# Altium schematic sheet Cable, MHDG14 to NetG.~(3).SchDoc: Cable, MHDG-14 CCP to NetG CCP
size B; ApprovedBy: Hans Thomas; CheckedBy: Hans Thomas; Author: Hans Thomas; DrawnBy: Hans Thomas; Engineer: Hans Thomas; Organization: MBARI; DocumentNumber: 100221138; Revision: A; SheetNumber: 1; SheetTotal: 1; PageSetup: Record=PageOptions¦CenterHorizontal=True¦CenterVertical=True¦PrintScale=0.72¦XCorrection=1.00¦YCorrection=1.00¦PrintKind=0¦BorderSize=5000000¦LeftOffset=0¦BottomOffset=0¦Orientation=2¦PaperLength=2794¦PaperWidth=2159¦Scale=100¦PaperSource=15¦PrintQuality=-3¦MediaType=1¦DitherType=0¦PrintScaleMode=1¦PaperKind=Letter (8.5 x 11 in)¦PaperIndex=1
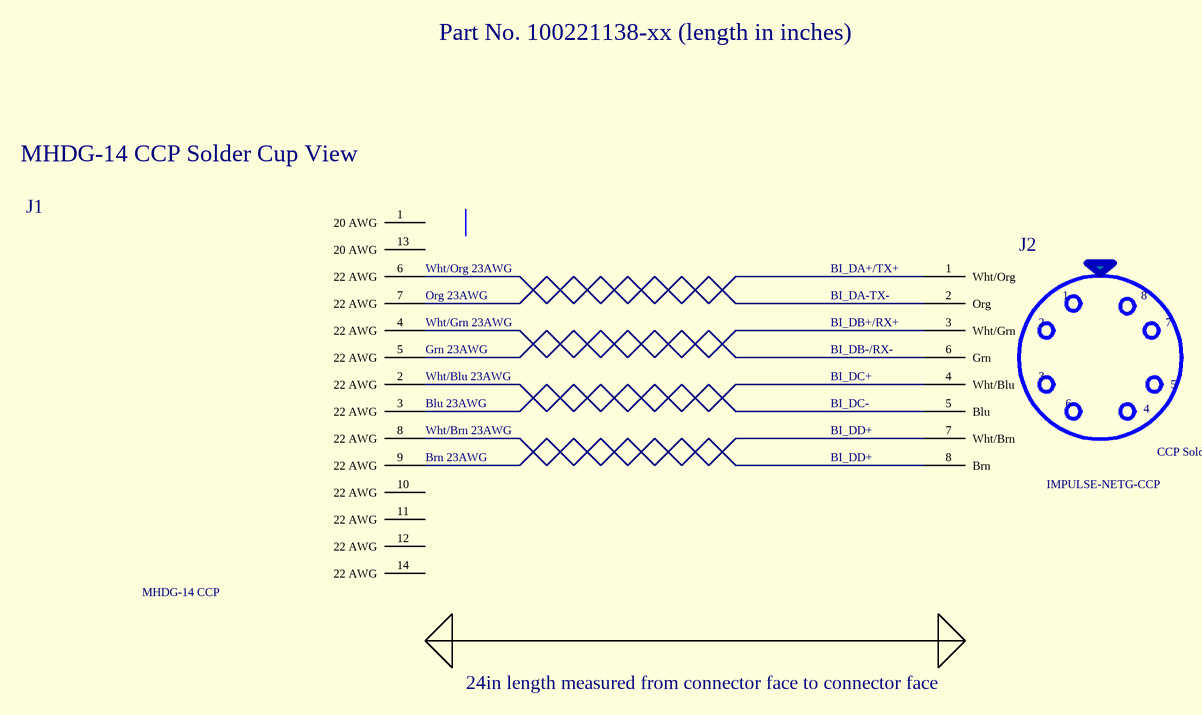
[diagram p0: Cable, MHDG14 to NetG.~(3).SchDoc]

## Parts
J1  MHDG-14 CCP
J2  IMPULSE-NETG-CCP

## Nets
NetJ1_2: J1.2(22_AWG) J2.4(Wht/Blu)
NetJ1_3: J1.3(22_AWG) J2.5(Blu)
NetJ1_4: J1.4(22_AWG) J2.3(Wht/Grn)
NetJ1_5: J1.5(22_AWG) J2.6(Grn)
NetJ1_6: J1.6(22_AWG) J2.1(Wht/Org)
NetJ1_7: J1.7(22_AWG) J2.2(Org)
NetJ1_8: J1.8(22_AWG) J2.7(Wht/Brn)
NetJ1_9: J1.9(22_AWG) J2.8(Brn)

Not connected (* = marked no-connect by the designer): J1 1(20_AWG) 10(22_AWG) 11(22_AWG) 12(22_AWG) 13(20_AWG) 14(22_AWG)

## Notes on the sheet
- Part No. 100221138-xx (length in inches)
- MHDG-14 CCP Solder Cup View
- (near J1) Wht/Org 23AWG
- (near J1) Org 23AWG
- BI_DA+/TX+
- BI_DA-TX-
- (near J1) Wht/Grn 23AWG
- (near J1) Grn 23AWG
- BI_DB+/RX+
- BI_DB-/RX-
- (near J1) Wht/Blu 23AWG
- (near J1) Blu 23AWG
- (near J1) Wht/Brn 23AWG
- BI_DC+
- BI_DC-
- BI_DD+
- (near J1) Brn 23AWG
- 24in length measured from connector face to connector face

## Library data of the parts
J1 = MHDG-14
